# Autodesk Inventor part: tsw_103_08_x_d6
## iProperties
Created: 2006-03
Part Number: tsw_103_08_x_d6
Document SubType Name: Modeling
Designer: Elise Moss
Author: Elise Moss
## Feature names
1. Base1
